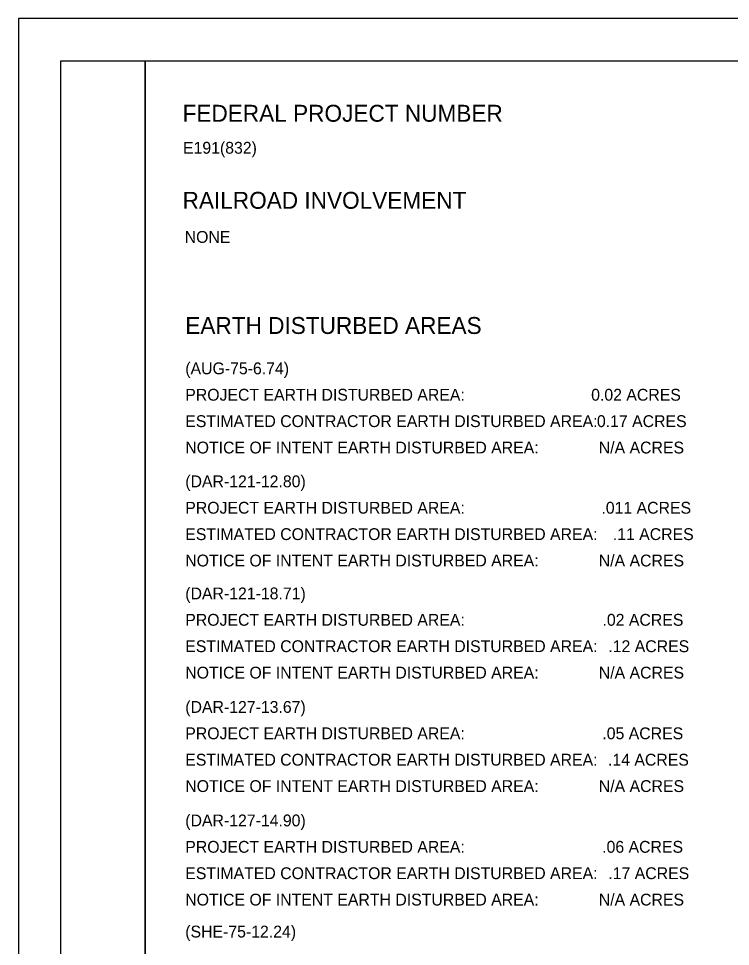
# Model space of a CAD drawing. Extents: x 0 to 34, y 0 to 22.
# Drawn here: x 0 to 8.42, y 11.03 to 22 of the extents above; entities that cross this region are included whole.
import ezdxf

# ---------------------------------------------------------------- set-up
doc = ezdxf.new("R2010")
doc.units = 0
for name, color, linetype in [('Default', 7, 'Continuous'), ('SH_Border', 7, 'Continuous'), ('SH_Cut_Line', 7, 'Continuous'), ('SH_Text', 7, 'Continuous')]:
    doc.layers.add(name, color=color, linetype=linetype)

msp = doc.modelspace()

# ---------------------------------------------------------------- linework, layer by layer
at = {"layer": 'SH_Border'}
for points in [[(0.5, 21.5), (1.5, 21.5), (1.5, 0.5), (0.5, 0.5)], [(1.5, 21.5), (33.5, 21.5), (33.5, 0.5), (1.5, 0.5)]]:
    msp.add_lwpolyline(points, close=True, dxfattribs=at)
at = {"layer": 'SH_Cut_Line'}
msp.add_lwpolyline([(0, 0), (34, 0), (34, 22), (0, 22)], close=True, dxfattribs=at)

# ---------------------------------------------------------------- texts
at = {"layer": 'Default'}
for s, p in [('E191(832)', (1.946, 20.402)), ('NONE', (1.966, 19.348))]:
    msp.add_text(s, height=0.14, dxfattribs=at).set_placement(p)
at = {"layer": 'SH_Text'}
for s, height, p in [('FEDERAL PROJECT NUMBER', 0.2, (1.941, 20.78)), ('RAILROAD INVOLVEMENT', 0.2, (1.941, 19.751)), ('EARTH DISTURBED AREAS', 0.2, (1.973, 18.271)), ('(AUG-75-6.74)', 0.14, (1.973, 17.794)), ('PROJECT EARTH DISTURBED AREA:', 0.14, (1.973, 17.482)), ('0.02 ACRES', 0.14, (6.776, 17.482)), ('ESTIMATED CONTRACTOR EARTH DISTURBED AREA:', 0.14, (1.973, 17.17)), ('0.17 ACRES', 0.14, (6.844, 17.17)), ('N/A ACRES', 0.14, (6.866, 16.858)), ('NOTICE OF INTENT EARTH DISTURBED AREA:', 0.14, (1.973, 16.858)), ('(DAR-121-12.80)', 0.14, (1.973, 16.458)), ('PROJECT EARTH DISTURBED AREA:', 0.14, (1.973, 16.146)), ('.011 ACRES', 0.14, (6.897, 16.146)), ('ESTIMATED CONTRACTOR EARTH DISTURBED AREA:', 0.14, (1.973, 15.834)), ('.11 ACRES', 0.14, (7.032, 15.834)), ('NOTICE OF INTENT EARTH DISTURBED AREA:', 0.14, (1.973, 15.522)), ('N/A ACRES', 0.14, (6.866, 15.522)), ('(DAR-121-18.71)', 0.14, (1.973, 15.133)), ('PROJECT EARTH DISTURBED AREA:', 0.14, (1.973, 14.821)), ('.02 ACRES', 0.14, (6.91, 14.821)), ('ESTIMATED CONTRACTOR EARTH DISTURBED AREA:', 0.14, (1.973, 14.509)), ('.12 ACRES', 0.14, (6.979, 14.509)), ('NOTICE OF INTENT EARTH DISTURBED AREA:', 0.14, (1.973, 14.197)), ('N/A ACRES', 0.14, (6.866, 14.197)), ('(DAR-127-13.67)', 0.14, (1.973, 13.791)), ('PROJECT EARTH DISTURBED AREA:', 0.14, (1.973, 13.479)), ('.05 ACRES', 0.14, (6.908, 13.479)), ('ESTIMATED CONTRACTOR EARTH DISTURBED AREA:', 0.14, (1.973, 13.167)), ('.14 ACRES', 0.14, (6.975, 13.167)), ('NOTICE OF INTENT EARTH DISTURBED AREA:', 0.14, (1.973, 12.855)), ('N/A ACRES', 0.14, (6.866, 12.855)), ('(DAR-127-14.90)', 0.14, (1.973, 12.449)), ('PROJECT EARTH DISTURBED AREA:', 0.14, (1.973, 12.137)), ('.06 ACRES', 0.14, (6.906, 12.137)), ('ESTIMATED CONTRACTOR EARTH DISTURBED AREA:', 0.14, (1.973, 11.825)), ('.17 ACRES', 0.14, (6.979, 11.825)), ('NOTICE OF INTENT EARTH DISTURBED AREA:', 0.14, (1.973, 11.513)), ('N/A ACRES', 0.14, (6.866, 11.513)), ('(SHE-75-12.24)', 0.14, (1.973, 11.135))]:
    msp.add_text(s, height=height, dxfattribs=at).set_placement(p)

doc.saveas('drawing.dxf')
